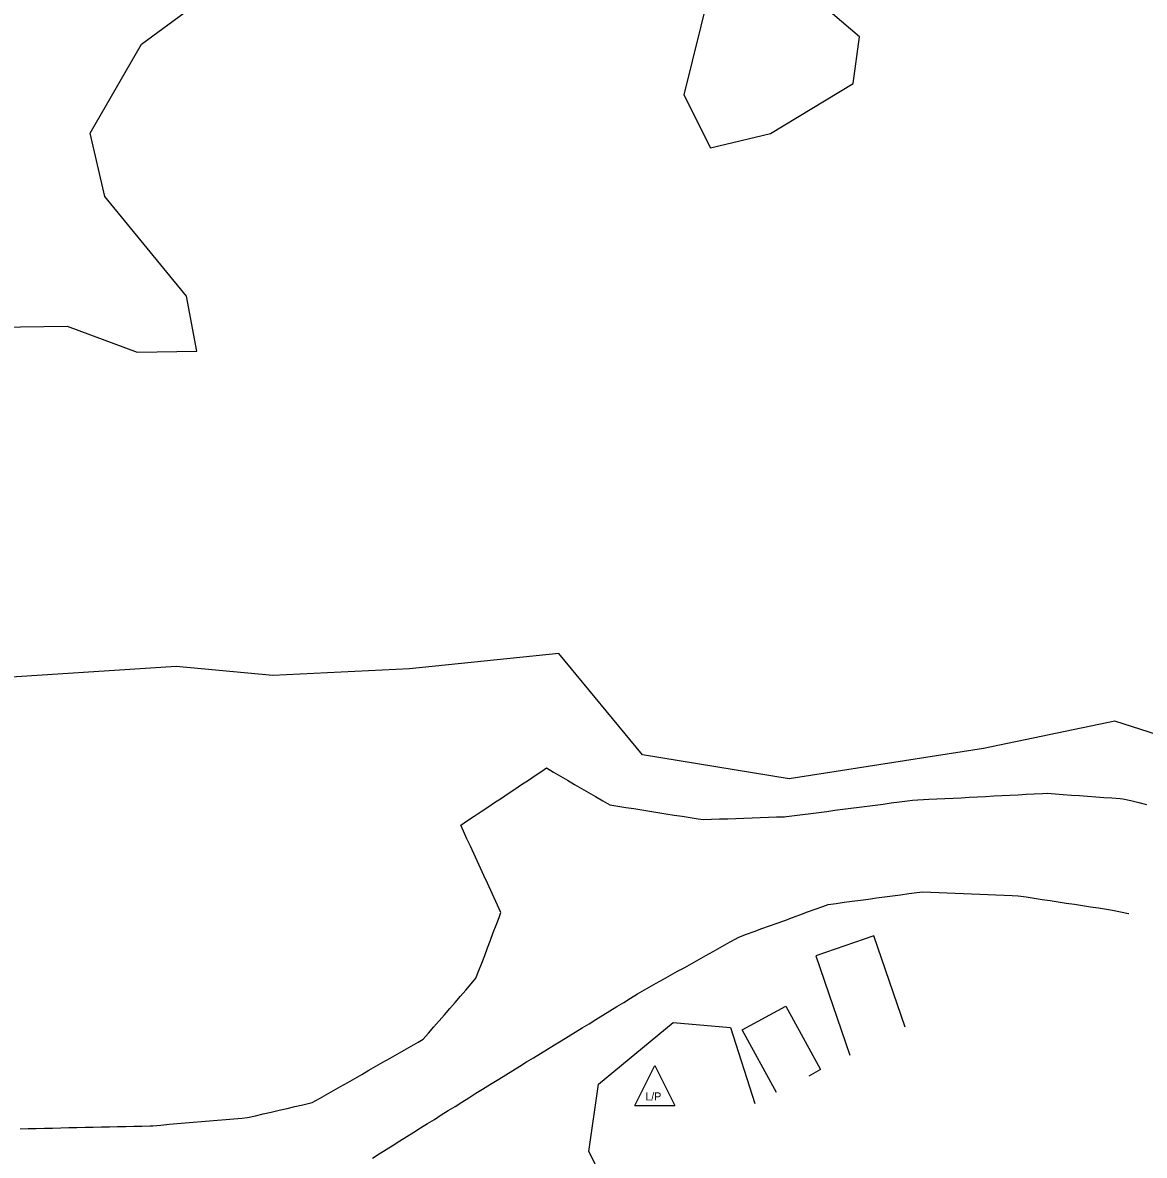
# Model space of a CAD drawing. Extents: x 1901471 to 1963503, y 756461 to 799997.
# Drawn here: x 1928441.4 to 1928579.4, y 772212.5 to 772351.8 of the extents above; entities that cross this region are included whole.
import ezdxf

# ---------------------------------------------------------------- set-up
doc = ezdxf.new("R2010")
doc.units = 0
for name, color, linetype in [('RD_EX_Bldg', 7, 'Continuous'), ('RD_EX_Driveway', 7, 'Continuous'), ('RD_EX_UT', 7, 'Continuous'), ('RD_EX_VEG', 7, 'Continuous'), ('RD_HC_Cl', 7, 'Continuous')]:
    doc.layers.add(name, color=color, linetype=linetype)

# ---------------------------------------------------------------- blocks, each defined once
blk = doc.blocks.new('LP')
at = {"layer": 'RD_EX_UT'}
for p, q in [((-5, -3.72), (0, 6.28)), ((0, 6.28), (5, -3.72)), ((-5, -3.72), (5, -3.72))]:
    blk.add_line(p, q, dxfattribs=at)
blk.add_text('L/P', height=2, dxfattribs=at).set_placement((-2.4, -2.44))

msp = doc.modelspace()

# ---------------------------------------------------------------- linework, layer by layer
at = {"layer": 'RD_EX_Bldg'}
for points in [[(1928549.96, 772228.26), (1928546.11, 772239.5), (1928538.96, 772237.05), (1928543.15, 772224.81)], [(1928534.14, 772220.24), (1928529.92, 772227.92), (1928535.26, 772230.85), (1928539.54, 772223.04), (1928538.1, 772222.25)]]:
    msp.add_lwpolyline(points, dxfattribs=at)
at = {"layer": 'RD_EX_Driveway'}
for points in [[(1928441.11, 772215.77), (1928442.11, 772215.79), (1928443.11, 772215.82), (1928444.11, 772215.84), (1928445.11, 772215.86), (1928446.11, 772215.89), (1928447.11, 772215.91), (1928448.11, 772215.93), (1928449.11, 772215.95), (1928450.11, 772215.98), (1928451.11, 772216), (1928452.11, 772216.02), (1928453.11, 772216.05), (1928454.11, 772216.07), (1928455.11, 772216.09), (1928456.1, 772216.11), (1928457.1, 772216.14), (1928457.43, 772216.15), (1928458.43, 772216.23), (1928459.43, 772216.32), (1928460.42, 772216.4), (1928461.42, 772216.49), (1928462.41, 772216.57), (1928463.41, 772216.66), (1928464.41, 772216.74), (1928465.4, 772216.83), (1928466.4, 772216.91), (1928467.4, 772217), (1928468.39, 772217.08), (1928469.07, 772217.14), (1928470.05, 772217.37), (1928471.02, 772217.59), (1928471.99, 772217.82), (1928472.97, 772218.05), (1928473.94, 772218.27), (1928474.92, 772218.5), (1928475.89, 772218.72), (1928476.86, 772218.95), (1928477.05, 772218.99), (1928477.92, 772219.49), (1928478.79, 772219.98), (1928479.66, 772220.48), (1928480.53, 772220.97), (1928481.4, 772221.47), (1928482.27, 772221.97), (1928483.13, 772222.46), (1928484, 772222.96), (1928484.87, 772223.45), (1928485.74, 772223.95), (1928486.61, 772224.44), (1928487.48, 772224.94), (1928488.35, 772225.43), (1928489.22, 772225.93), (1928490.08, 772226.42), (1928490.7, 772226.77), (1928491.35, 772227.53), (1928492.01, 772228.29), (1928492.66, 772229.04), (1928493.31, 772229.8), (1928493.97, 772230.56), (1928494.62, 772231.31), (1928495.27, 772232.07), (1928495.93, 772232.83), (1928496.58, 772233.58), (1928497.18, 772234.28), (1928497.54, 772235.22), (1928497.89, 772236.15), (1928498.25, 772237.09), (1928498.6, 772238.02), (1928498.96, 772238.95), (1928499.31, 772239.89), (1928499.67, 772240.82), (1928500.02, 772241.76), (1928500.25, 772242.36), (1928499.83, 772243.26), (1928499.41, 772244.17), (1928499, 772245.08), (1928498.58, 772245.99), (1928498.16, 772246.9), (1928497.74, 772247.81), (1928497.33, 772248.71), (1928496.91, 772249.62), (1928496.49, 772250.53), (1928496.07, 772251.44), (1928495.65, 772252.35), (1928495.31, 772253.11), (1928496.14, 772253.66), (1928496.97, 772254.21), (1928497.8, 772254.77), (1928498.63, 772255.32), (1928499.47, 772255.88), (1928500.3, 772256.43), (1928501.13, 772256.98), (1928501.96, 772257.54), (1928502.79, 772258.09), (1928503.62, 772258.65), (1928504.46, 772259.2), (1928505.29, 772259.76), (1928505.85, 772260.13), (1928506.71, 772259.62), (1928507.58, 772259.12), (1928508.44, 772258.62), (1928509.3, 772258.12), (1928510.17, 772257.61), (1928511.03, 772257.11), (1928511.89, 772256.61), (1928512.76, 772256.1), (1928513.63, 772255.59), (1928514.62, 772255.44), (1928515.6, 772255.28), (1928516.59, 772255.13), (1928517.58, 772254.97), (1928518.57, 772254.82), (1928519.55, 772254.66), (1928520.54, 772254.51), (1928521.53, 772254.35), (1928522.52, 772254.2), (1928523.51, 772254.04), (1928524.49, 772253.89), (1928525.14, 772253.78), (1928526.14, 772253.82), (1928527.14, 772253.86), (1928528.14, 772253.89), (1928529.14, 772253.93), (1928530.13, 772253.96), (1928531.13, 772254), (1928532.13, 772254.03), (1928533.13, 772254.07), (1928534.13, 772254.11), (1928535.13, 772254.14), (1928535.37, 772254.15), (1928536.36, 772254.28), (1928537.35, 772254.41), (1928538.34, 772254.54), (1928539.33, 772254.67), (1928540.32, 772254.8), (1928541.31, 772254.93), (1928542.3, 772255.06), (1928543.29, 772255.19), (1928544.28, 772255.32), (1928545.28, 772255.44), (1928546.27, 772255.57), (1928547.26, 772255.7), (1928548.25, 772255.83), (1928549.24, 772255.96), (1928550.23, 772256.09), (1928550.86, 772256.17), (1928552.85, 772256.28), (1928553.85, 772256.33), (1928554.85, 772256.38), (1928555.85, 772256.43), (1928556.84, 772256.48), (1928557.84, 772256.54), (1928558.84, 772256.59), (1928559.84, 772256.64), (1928560.84, 772256.69), (1928561.84, 772256.74), (1928562.83, 772256.8), (1928563.83, 772256.85), (1928564.83, 772256.9), (1928565.83, 772256.95), (1928566.83, 772257), (1928567.4, 772257.03), (1928568.4, 772256.96), (1928569.4, 772256.89), (1928570.4, 772256.81), (1928571.39, 772256.74), (1928572.39, 772256.67), (1928573.39, 772256.6), (1928574.39, 772256.52), (1928575.38, 772256.45), (1928576.38, 772256.38), (1928576.73, 772256.35), (1928577.7, 772256.12), (1928578.67, 772255.88), (1928579.64, 772255.65)], [(1928484.44, 772212.15), (1928485.29, 772212.68), (1928486.14, 772213.21), (1928486.98, 772213.74), (1928487.83, 772214.27), (1928488.68, 772214.81), (1928489.52, 772215.34), (1928490.37, 772215.87), (1928491.22, 772216.4), (1928492.06, 772216.93), (1928492.91, 772217.47), (1928493.76, 772218), (1928494.6, 772218.53), (1928495.45, 772219.06), (1928496.3, 772219.59), (1928497.14, 772220.13), (1928497.99, 772220.66), (1928498.29, 772220.85), (1928499.15, 772221.37), (1928500, 772221.89), (1928500.85, 772222.42), (1928501.7, 772222.94), (1928502.56, 772223.46), (1928503.41, 772223.99), (1928504.26, 772224.51), (1928505.11, 772225.03), (1928505.97, 772225.56), (1928506.82, 772226.08), (1928507.67, 772226.6), (1928508.52, 772227.12), (1928509.37, 772227.65), (1928510.23, 772228.17), (1928511.08, 772228.69), (1928511.93, 772229.22), (1928512.78, 772229.74), (1928513.64, 772230.26), (1928514.49, 772230.79), (1928515.34, 772231.31), (1928516.19, 772231.83), (1928517.05, 772232.35), (1928517.6, 772232.7), (1928518.48, 772233.18), (1928519.35, 772233.67), (1928520.22, 772234.16), (1928521.09, 772234.65), (1928521.97, 772235.13), (1928522.84, 772235.62), (1928523.71, 772236.11), (1928524.59, 772236.6), (1928525.46, 772237.09), (1928526.33, 772237.57), (1928527.2, 772238.06), (1928528.08, 772238.55), (1928528.95, 772239.04), (1928529.51, 772239.35), (1928530.44, 772239.69), (1928531.38, 772240.03), (1928532.32, 772240.38), (1928533.26, 772240.72), (1928534.2, 772241.06), (1928535.14, 772241.4), (1928536.08, 772241.75), (1928537.02, 772242.09), (1928537.96, 772242.43), (1928538.9, 772242.77), (1928539.84, 772243.12), (1928540.48, 772243.35), (1928541.47, 772243.49), (1928542.46, 772243.62), (1928543.45, 772243.75), (1928544.45, 772243.88), (1928545.44, 772244.02), (1928546.43, 772244.15), (1928547.42, 772244.28), (1928548.41, 772244.42), (1928549.4, 772244.55), (1928550.39, 772244.68), (1928551.38, 772244.82), (1928552.12, 772244.92), (1928553.12, 772244.87), (1928554.12, 772244.83), (1928555.12, 772244.79), (1928556.12, 772244.75), (1928557.12, 772244.71), (1928558.12, 772244.67), (1928559.12, 772244.63), (1928560.12, 772244.58), (1928561.12, 772244.54), (1928562.12, 772244.5), (1928563.11, 772244.46), (1928563.84, 772244.43), (1928564.83, 772244.28), (1928565.82, 772244.13), (1928566.81, 772243.98), (1928567.8, 772243.82), (1928568.78, 772243.67), (1928569.77, 772243.52), (1928570.76, 772243.37), (1928571.75, 772243.22), (1928572.74, 772243.07), (1928573.73, 772242.92), (1928574.72, 772242.77), (1928575.45, 772242.65), (1928576.43, 772242.44), (1928577.41, 772242.23), (1928577.45, 772242.22)]]:
    msp.add_lwpolyline(points, dxfattribs=at)
at = {"layer": 'RD_EX_VEG'}
for points in [[(1928429.61, 772314.21), (1928446.91, 772314.47), (1928455.5, 772311.25), (1928462.86, 772311.37), (1928461.59, 772318.16), (1928451.54, 772330.38), (1928449.75, 772338.19), (1928456.05, 772349.11), (1928468.55, 772358.36)], [(1928525.85, 772355.53), (1928522.74, 772342.9), (1928526.03, 772336.38), (1928533.39, 772338.16), (1928543.56, 772344.29), (1928544.34, 772350.02), (1928534.67, 772358.29)], [(1928589.44, 772261.49), (1928575.74, 772265.87), (1928559.57, 772262.54), (1928535.67, 772258.81), (1928517.66, 772261.76), (1928507.37, 772274.19), (1928489, 772272.33), (1928472.21, 772271.49), (1928460.31, 772272.6), (1928436.22, 772271.07)], [(1928512.86, 772209.43), (1928511.06, 772212.96), (1928512.26, 772221.27), (1928521.44, 772228.85), (1928528.47, 772228.24), (1928531.47, 772218.88)]]:
    msp.add_lwpolyline(points, dxfattribs=at)
at = {"layer": 'RD_HC_Cl'}
for centre, radius, start, end in [((1933934.02, 762479.74), 11482.38, 112.01316, 122.84589), ((1933920.67, 762509.14), 11420.5, 112.014247, 122.846378), ((1933910.03, 762523.4), 11373.86, 112.013249, 123.541888)]:
    msp.add_arc(centre, radius, start, end, dxfattribs=at)

# ---------------------------------------------------------------- block references
at = {"layer": 'RD_EX_UT', "xscale": 0.4921259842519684, "yscale": 0.4921259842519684}
msp.add_blockref('LP', (1928519.18, 772220.46), dxfattribs=at)

doc.saveas('drawing.dxf')
